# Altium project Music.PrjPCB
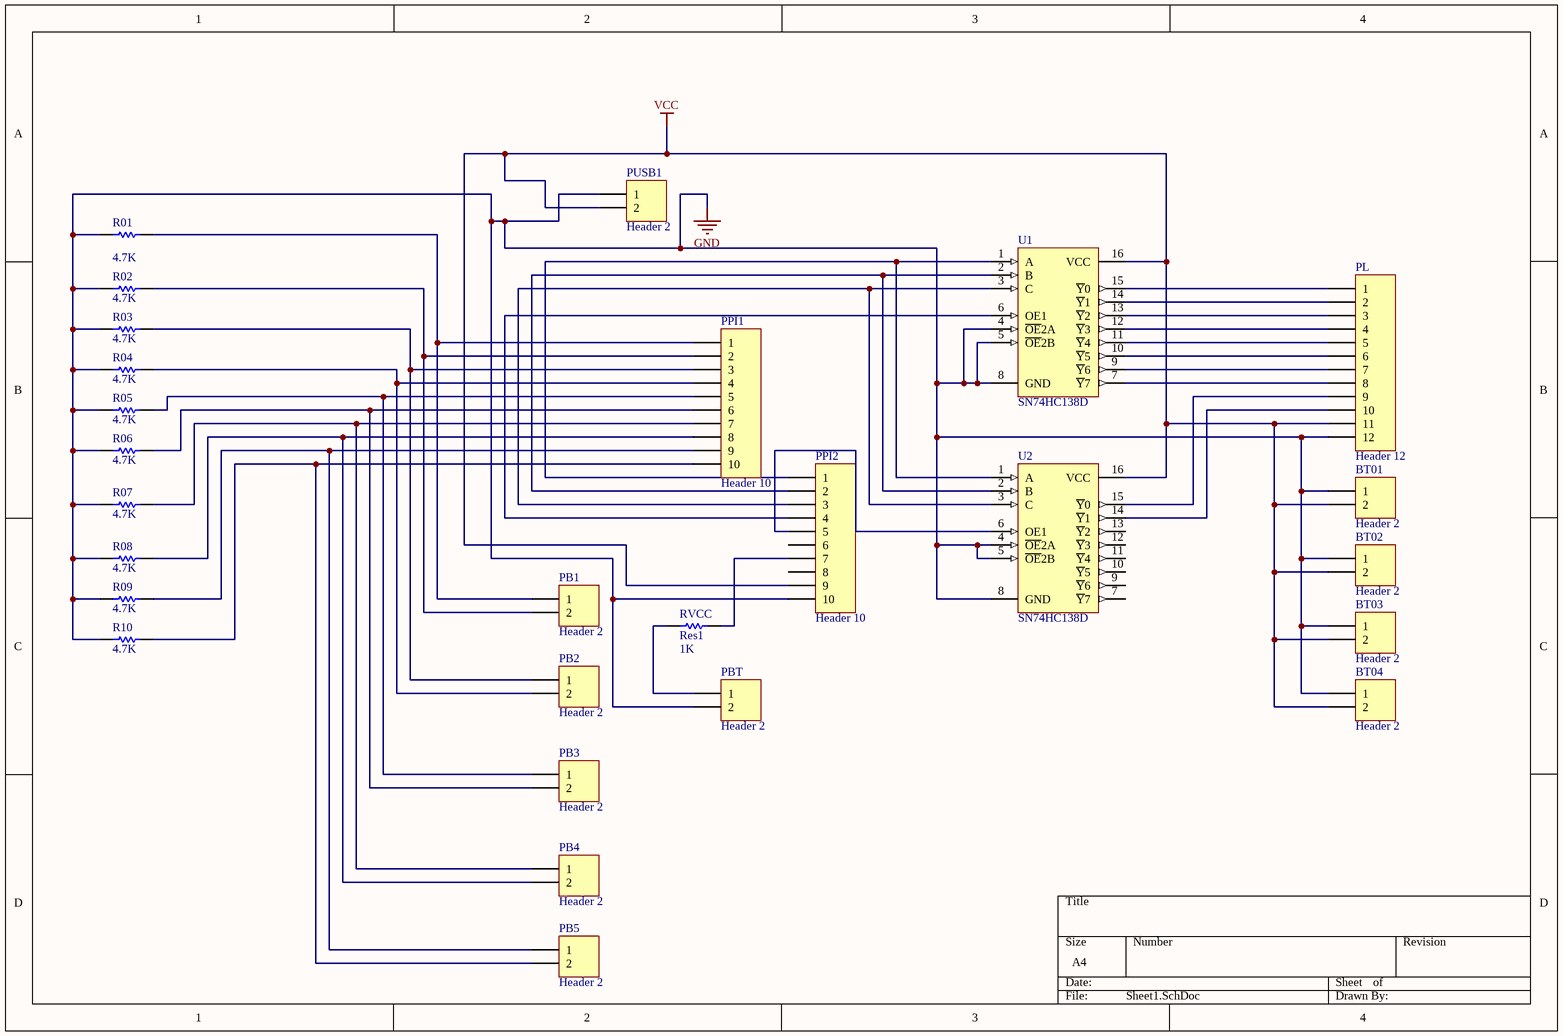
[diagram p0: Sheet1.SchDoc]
1 sheet, 27 parts. Net scope: global (net labels, ports and power ports of the same name join across sheets).
Board file: PCB1.PcbDoc

## Sheet Sheet1.SchDoc
size A4

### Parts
BT01  Header 2  [HDR1X2]
BT02  Header 2  [HDR1X2]
BT03  Header 2  [HDR1X2]
BT04  Header 2  [HDR1X2]
PB1  Header 2  [SPST-2]
PB2  Header 2  [SPST-2]
PB3  Header 2  [SPST-2]
PB4  Header 2  [SPST-2]
PB5  Header 2  [SPST-2]
PBT  Header 2  [SPST-2]
PL  Header 12  [HDR1X12]
PPI1  Header 10  [HDR1X10]
PPI2  Header 10  [HDR1X10]
PUSB1  Header 2  [SPST-2]
R01  value 4.7K  [3216[1206]]  (hidden comment: Res1)
R02  value 4.7K  [3216[1206]]  (hidden comment: Res1)
R03  value 4.7K  [3216[1206]]  (hidden comment: Res1)
R04  value 4.7K  [3216[1206]]  (hidden comment: Res1)
R05  value 4.7K  [3216[1206]]  (hidden comment: Res1)
R06  value 4.7K  [3216[1206]]  (hidden comment: Res1)
R07  value 4.7K  [3216[1206]]  (hidden comment: Res1)
R08  value 4.7K  [3216[1206]]  (hidden comment: Res1)
R09  value 4.7K  [3216[1206]]  (hidden comment: Res1)
R10  value 4.7K  [3216[1206]]  (hidden comment: Res1)
RVCC  Res1  value 1K  [3216[1206]]
U1  SN74HC138D  [DIP-16]
U2  SN74HC138D  [DIP-16]

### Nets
GND: BT01.1 BT02.1 BT03.1 BT04.1 PBT.2 PL.12 PPI2.10 PUSB1.1 R01.1 R02.1 R03.1 R04.1 R05.1 R06.1 R07.1 R08.1 R09.1 R10.1 U1.4(~{OE}2A) U1.5(~{OE}2B) U1.8(GND) U2.4(~{OE}2A) U2.5(~{OE}2B) U2.8(GND)
VCC: BT01.2 BT02.2 BT03.2 BT04.2 PL.11 PPI2.9 PUSB1.2 U1.16(VCC) U2.16(VCC)
NetPB1_1: PB1.1 PPI1.1 R01.2
NetPB1_2: PB1.2 PPI1.2 R02.2
NetPB2_1: PB2.1 PPI1.3 R03.2
NetPB2_2: PB2.2 PPI1.4 R04.2
NetPB3_1: PB3.1 PPI1.5 R05.2
NetPB3_2: PB3.2 PPI1.6 R06.2
NetPB4_1: PB4.1 PPI1.7 R07.2
NetPB4_2: PB4.2 PPI1.8 R08.2
NetPB5_1: PB5.1 PPI1.9 R09.2
NetPB5_2: PB5.2 PPI1.10 R10.2
NetPBT_1: PBT.1 RVCC.1
NetPL_1: PL.1 U1.15(~{Y}0)
NetPL_2: PL.2 U1.14(~{Y}1)
NetPL_3: PL.3 U1.13(~{Y}2)
NetPL_4: PL.4 U1.12(~{Y}3)
NetPL_5: PL.5 U1.11(~{Y}4)
NetPL_6: PL.6 U1.10(~{Y}5)
NetPL_7: PL.7 U1.9(~{Y}6)
NetPL_8: PL.8 U1.7(~{Y}7)
NetPL_9: PL.9 U2.15(~{Y}0)
NetPL_10: PL.10 U2.14(~{Y}1)
NetPPI2_1: PPI2.1 U1.1(A) U2.1(A)
NetPPI2_2: PPI2.2 U1.2(B) U2.2(B)
NetPPI2_3: PPI2.3 U1.3(C) U2.3(C)
NetPPI2_4: PPI2.4 U1.6(OE1)
NetPPI2_5: PPI2.5 U2.6(OE1)
NetPPI2_7: PPI2.7 RVCC.2

Not connected (* = marked no-connect by the designer): PPI2 6 8; U2 7(~{Y}7) 9(~{Y}6) 10(~{Y}5) 11(~{Y}4) 12(~{Y}3) 13(~{Y}2)

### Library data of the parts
BT01 BT02 BT03 BT04 PB1-PB5 PBT PUSB1 = Header 2: Header, 2-Pin
PL = Header 12: Header, 12-Pin
PPI1 PPI2 = Header 10: Header, 10-Pin
R01 R02 R03 R04 R05 R06 R07 R08 R09 R10 RVCC = Res1: Resistor
U1 U2 = SN74HC138D: 3-Line to 8-Line Decoder / Demultiplexer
